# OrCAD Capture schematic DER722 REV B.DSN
size Custom; title: 12V 0.2A LNK-TN2-900; rev: B
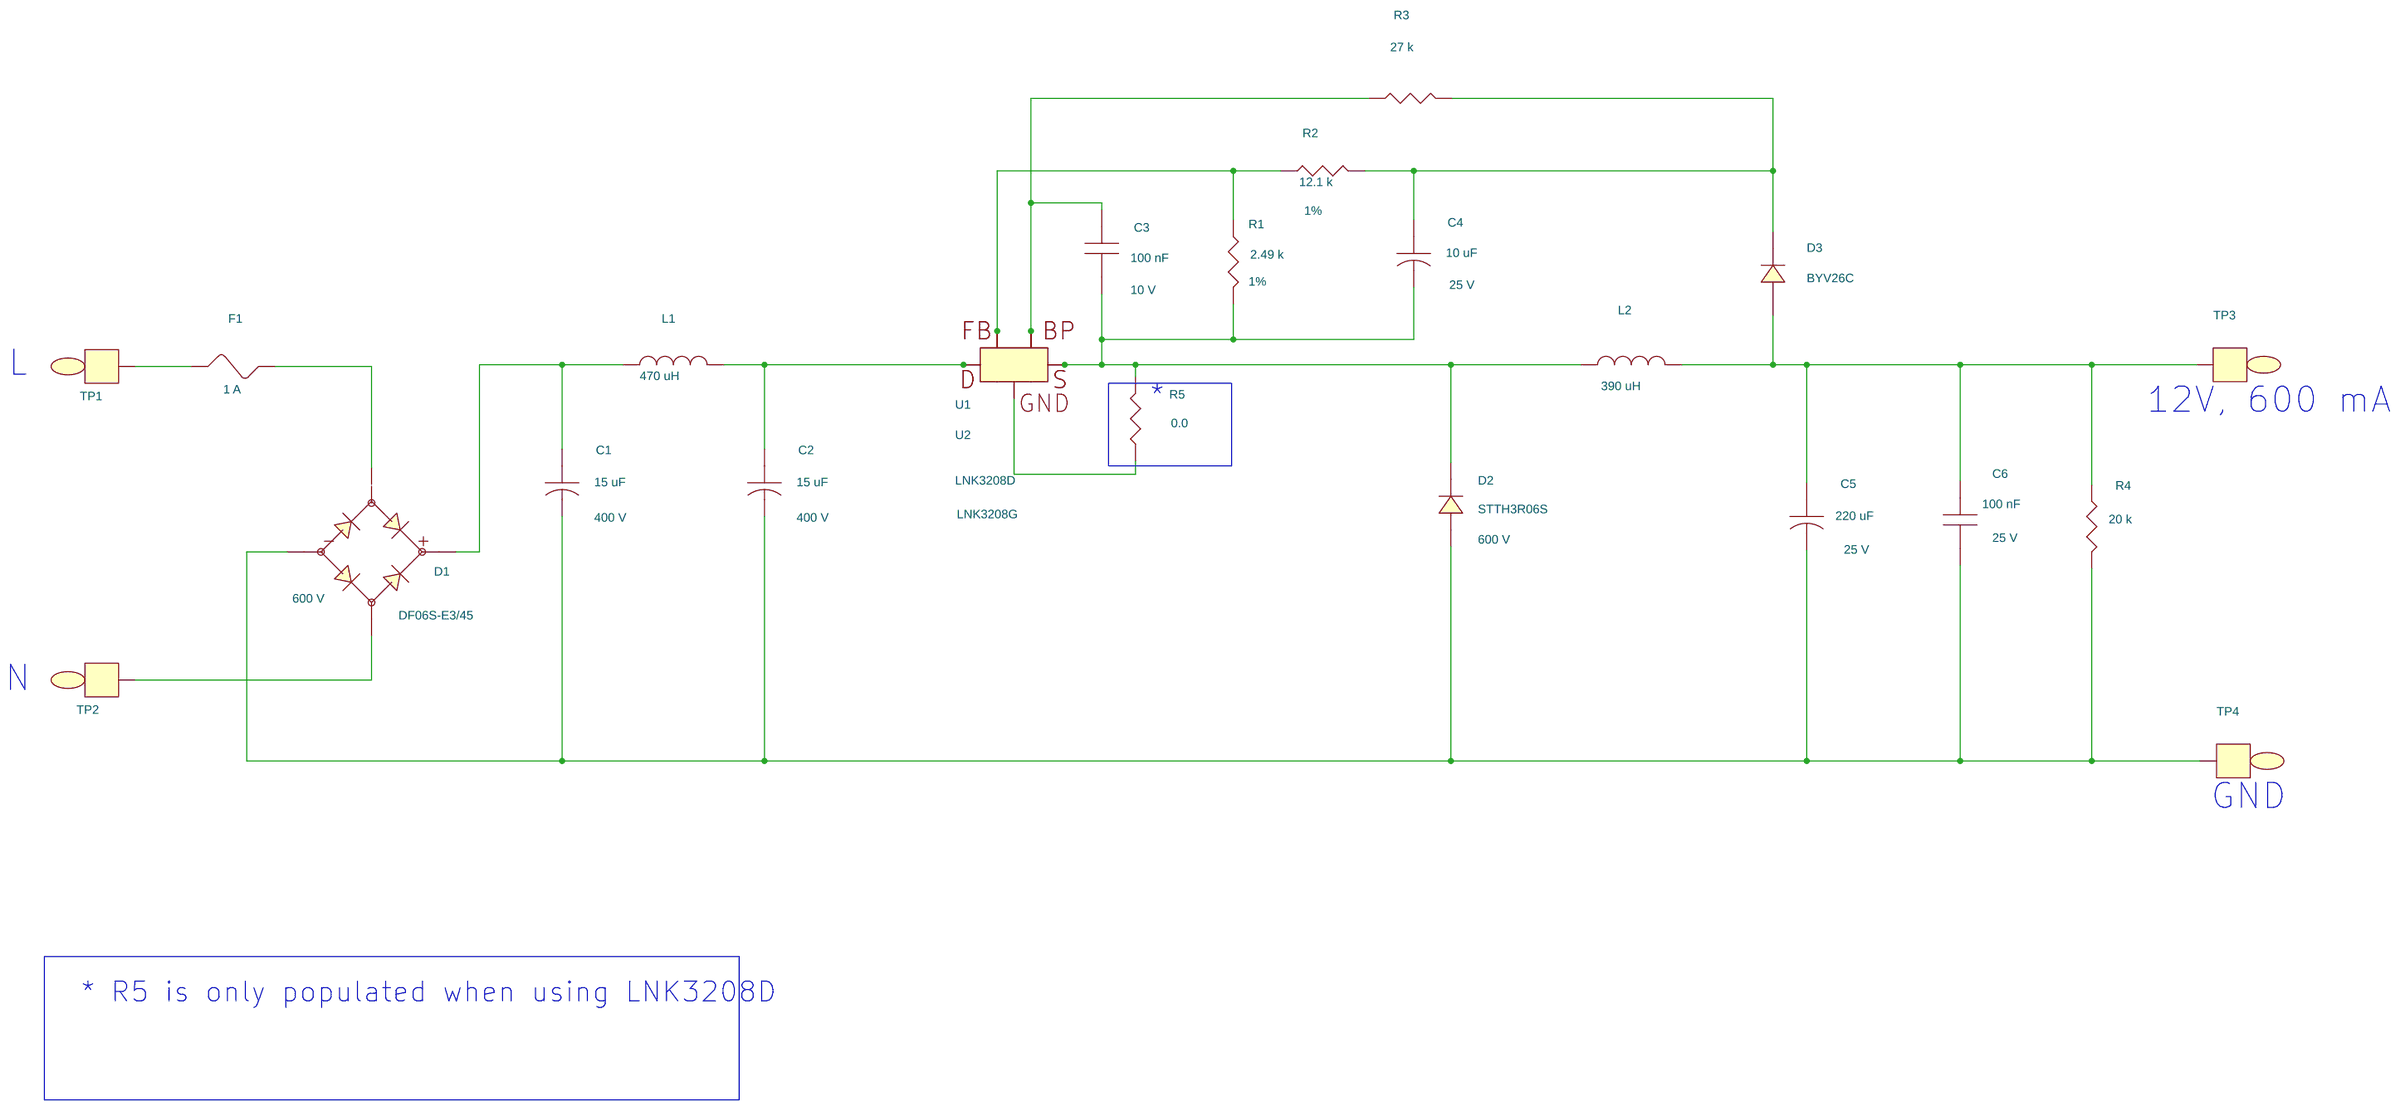
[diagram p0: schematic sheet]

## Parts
C1  15 uF  [pipolcapcyld400ls200040]
C2  15 uF  [pipolcapcyld400ls200040]
C3  100 nF  [pismc0805]
C4  10 uF  [pipolcapclyd5mmls2mm025]
C5  220 uF  [pipolcapclyd320ls140030]
C6  100 nF  [pismc1206]
D1  DF06S-E3/45  [pismddfs]
D2  STTH3R06S  [pismdo214ab12]
D3  BYV26C  [pidv200x150x040sod57]
F1  1 A  [pi_rst_microfuse]
L1  470 uH  [pichoketokinvd276h413ls158d030]
L2  390 uH  [pichokevd13xxls5mmd050]
R1  2.49 k  [pismr0603]
R2  12.1 k  [pismr0603]
R3  27 k  [pismr0603]
R4  20 k  [pismr0805]
R5  0.0  [pismr0805]
TP1  WHT  [pitpkeystone125x125]
TP2  BLK  [pitpkeystone125x125]
TP3  RED  [pitpkeystone100x100]
TP4  BLK  [pitpkeystone100x100]
U1  LNK3208D  [pismso8dnshort5678]
U2  LNK3208G  [piicsmd8cshort567IPC]

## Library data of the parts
C1 C2 = CAP_POL: ALT_SYMBOLS: pipolcapclyd400x630ls200030h; Disp_Voltage: 400 V; FPLIST: pipolcapcyld400ls200040,pipolcapclyd400x630ls200030h; Part Number: 20-08745-00; Voltage: 400 V
C3 = CAP_NP: Disp_Voltage: 10 V; Part Number: 20-01399-00; Voltage: 10 V
C4 = CAP_POL: ALT_SYMBOLS: pipolcapclyd5mm030,pipolcapclyd5x5mm030H; Disp_Voltage: 25 V; FPLIST: pipolcapclyd5mmls2mm025,pipolcapclyd5mm030,pipolcapclyd5x5mm030H; Part Number: 20-01690-00; Voltage: 25 V
C5 = CAP_POL: ALT_SYMBOLS: pipolcapclyd320ls140030430h; Disp_Voltage: 25 V; FPLIST: pipolcapclyd320ls140030,pipolcapclyd320ls140030430h,pipolcapclyd320ls140030430h; Part Number: 20-00028-00; Voltage: 25 V
C6 = CAP_NP: Disp_Voltage: 25 V; Part Number: 20-08743-00; Voltage: 25 V
D1 = DIODE_BRIDGE_+-~~: Disp_Voltage: 600 V; Part Number: 15-00281-00
D2 = DIODE: Disp_Voltage: 600 V; Part Number: 15-00827-00
D3 = DIODE: ALT_SYMBOLS: pidax425x150040sod57,pidv200x150x040sod57r; FPLIST: pidv200x150x040sod57,pidax425x150040sod57,pidv200x150x040sod57r; Part Number: 15-00128-00
F1 = FUSE: ALT_SYMBOLS: pirstmicrofusehoz; FPLIST: pi_rst_microfuse,pirstmicrofusehoz; Part Number: 40-00053-00
L1 = INDUCTOR: Part Number: 30-00021-00
L2 = INDUCTOR: Part Number: 30-00511-00
R1 = R: Disp_Tol: 1%; Part Number: 05-01116-00
R2 = R: Disp_Tol: 1%; Part Number: 05-03190-00
R3 = R: Part Number: 05-01722-00
R4 = R: Part Number: 05-01550-00
R5 = R: ALT_SYMBOLS: pismr0805_1; FPLIST: pismr0805,pismr0805_1; Part Number: 05-03159-00
TP1 = TESTPOINT: Part Number: 35-00044-00
TP2 = TESTPOINT: Part Number: 35-00042-00
TP3 = TESTPOINT: Part Number: 35-00080-00
TP4 = TESTPOINT: ALT_SYMBOLS: TP_TH_CR2_D1_1; Part Number: 35-00079-00
U1 = LNK32XX_8C: Part Number: 10-01356-00
U2 = LNK32XX_8G: Part Number: 10-01352-00

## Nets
SOURCE: U1.6(SOURCE) U1.7(SOURCE) U1.8(SOURCE)
N4183667: C2.1 L1.2 U1.4(D) U2.4
N4183681: C1.2 C2.2 C5.2 C6.2 D1.2 D2.2 R4.2 TP4.1
N4183882: C3.2 C4.2 D2.1 L2.1 R1.2 R5.2 U1.5(S) U2.5
N4183892: C3.1 R3.1 U1.1(BP) U2.1
N4184371: R1.1 R2.1 U1.2(FB) U2.2
N4185002: C5.1 C6.1 D3.2 L2.2 R4.1 TP3.1
N4185015: C4.1 D3.1 R2.2 R3.2
N4189997: F1.2 TP1.1
N4191135: D1.3 F1.1
N4191219: C1.1 D1.1 L1.1
N4191491: D1.4 TP2.1
N4224221: R5.1 U2.8

Not connected (* = marked no-connect by the designer): U2 6 7

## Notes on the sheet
- L
- *
- 12V, 600 mA
- N
- GND
- * R5 is only populated when using LNK3208D
